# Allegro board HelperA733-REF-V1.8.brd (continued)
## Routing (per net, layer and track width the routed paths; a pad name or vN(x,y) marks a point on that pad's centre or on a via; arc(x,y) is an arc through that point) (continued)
PCIE-CLKREQN: length 35.6
  TOP w0.152: R229.2 44.01,60.15 43.66,60.5 Q10.2 43.66,63.45 43.61,63.5 v1(43.61,65.6) ; v1(61.01,65.5) 61.61,66.1 61.61,66.1 61.71,66.2 61.71,74.6 61.01,75.3 U1.131
  BOTTOM w0.152: v1(61.01,65.5) 60.11,66.4 48.73,66.4 47.11,64.78 44.43,64.78 v1(43.61,65.6)
PCIE-PERSTN: length 39.6
  TOP w0.152: U1.130 62.01,65.7 v1(61.81,65.5) ; v1(40.71,65.5) 40.56,65.35 Q11.2 40.56,60.68 R231.2
  BOTTOM w0.152: v1(40.71,65.5) 41.72,64.5 47.51,64.5 49.11,66.1 59.61,66.1 60.81,64.9 61.51,64.9 61.81,65.2 v1(61.81,65.5)
PCIE-WAKEN: length 29.3
  TOP w0.152: v1(61.01,66.4) 60.05,67.36 60.05,73.36 59.71,73.7 U1.132 ; R120.2 46.51,62.94 Q9.2 46.86,65.35 46.91,65.4 v1(46.91,65.3)
  BOTTOM w0.152: v1(46.91,65.3) 48.31,66.7 60.71,66.7 v1(61.01,66.4)
PERSTN: length 13.1
  TOP w0.152: J12.50 47.51,66.5 47.21,66.2 43.21,66.2 41.51,64.5 Q11.3 41.51,61.08 42.61,59.98 42.61,59.83 R232.2
PHYRSTB: length 23.3
  TOP w0.152: U10.12 110.92,76.7 110.02,75.8 CE7.2 109.44,76.17 ; 109.44,76.47 RE2.2 ; 109.44,76.47 109.44,76.32 ; 109.44,76.47 109.31,76.34 109.31,76.32 ; 109.44,76.32 109.31,76.32 ; 109.44,76.32 109.44,76.17 ; 109.44,76.17 109.29,76.32 ; 109.31,76.32 109.29,76.32 ; 109.29,76.32 107.05,76.32 106.34,75.61 101.66,75.61 99.91,77.36 93.67,77.36 93.01,76.7 U1.99
PK10: length 18.7
  TOP w0.152: J16.8 55.61,4.2 55.61,7 56.91,8.3 D57.6 D57.5 56.91,18.3 58.31,19.7 U1.186
PK11: length 15.4
  TOP w0.152: U1.187 58.21,18.7 57.41,17.9 D57.4 D57.7 57.41,8.2 56.11,6.9 56.11,5.7 J16.7
PK12: length 21.3
  TOP w0.152: U1.184 58.81,21.7 58.01,20.9 58.01,20.4 54.41,16.8 D58.2 D58.9 54.41,7.1 53.61,6.3 53.61,4.2 J16.10
PK13: length 17.9
  TOP w0.152: 58.81,20.7 U1.185 ; 58.81,20.7 54.91,16.8 D58.1 D58.10 54.91,6.9 54.11,6.1 54.11,5.7 J16.9 ; 58.81,20.7 58.73,20.7
PK16: length 16.7
  TOP w0.152: J16.6 57.61,4.2 57.61,6.2 58.42,7.01 58.42,8.5 58.41,8.51 D57.9 D57.2 58.41,12.5 59.71,13.8 62.31,13.8 63.01,14.5 U1.3
PK17: length 14.8
  TOP w0.152: U1.4 64.01,14.51 62.81,13.3 59.91,13.3 58.91,12.3 D57.1 D57.10 58.91,6.9 58.13,6.12 58.13,5.68 J16.5
PL12: length 37.9
  TOP w0.152: U1.171 58.81,34.7 57.41,33.3 57.41,20.8 53.61,17 v1(52.91,17) ; J16.16 47.61,4.2 47.61,7.6 48.91,8.9 D59.6 D59.5 48.91,13.6 v1(48.71,13.8)
  BOTTOM w0.152: v1(52.91,17) 51.91,17 v1(48.71,13.8)
PL13: length 37.1
  TOP w0.152: U1.170 58.81,35.7 57.11,34 57.11,20.88 53.83,17.6 v1(53.41,17.6) ; J16.15 48.13,5.68 48.13,7.52 49.41,8.8 D59.7 D59.4 49.41,14.1 v1(48.81,14.7)
  BOTTOM w0.152: v1(48.81,14.7) 49.21,14.7 52.11,17.6 v1(53.41,17.6)
PM5-BEEP: length 30.9
  TOP w0.152: v1(45.01,22.7) 45.01,24.7 44.49,25.23 R81.1 ; v1(56.51,22.6) 56.71,22.8 56.71,34.6 58.81,36.7 U1.169
  BOTTOM w0.152: v1(45.01,22.7) 46.31,21.4 50.71,21.4 51.41,22.1 56.01,22.1 v1(56.51,22.6)
PWRON: length 117.8
  TOP w0.152: v1(54.31,19) 55.9,20.59 55.9,23.39 56.41,23.9 56.41,35.68 58.43,37.7 U1.168 ; v1(102.91,14.64) 102.91,12.07 105.01,9.97 105.01,7.72 109.03,3.7 116.1,3.7 123.3,10.9 134.88,10.9 C46.1 135.19,10.07 135.15,10.04 D41.2 135.15,7.46 K2.2 135.31,7.62
  BOTTOM w0.152: v1(102.91,14.64) 102.3,15.26 98.06,15.26 94.8,18.52 55.35,18.52 54.87,19 v1(54.31,19)
REFCLKN: length 12.2
  TOP w0.152: 49.41,78.88 49.51,78.97 R235.1 49.41,78.9 ; 49.41,78.88 49.41,78.1 R333.1 49.23,77.75 49.23,77.3 49.31,77.23 49.85,77.23 50.35,76.73 50.35,73.75 50.05,73.44 48.65,73.44 48.38,73.71 48.38,74.24 48.26,74.36 J12.53 ; 49.41,78.88 49.41,78.9 ; 49.41,78.9 49.41,79.78 CB11.2 R237.2
REFCLKP: length 11.6
  TOP w0.152: R236.2 CB10.2 48.81,79.88 48.81,78.97 48.61,78.97 48.54,78.9 48.81,78.9 48.81,78.38 48.64,78.21 48.64,78.1 48.54,78.1 48.98,77.66 48.98,77.19 49.2,76.97 49.75,76.97 50.09,76.63 50.09,73.84 49.94,73.69 48.76,73.69 48.64,73.82 48.64,74.25 48.76,74.37 J12.55
RGMII0-CLK-25M: length 32.2
  TOP w0.203: R86.1 118.89,77.1 v1(118.89,77.1) ; v1(117.86,67.72) 117.66,67.72 115.49,65.55 103.15,65.55 99.31,61.7 U1.82
  BOTTOM w0.203: v1(118.89,77.1) 117.5,75.7 117.5,67.99 117.75,67.73 117.84,67.68 v1(117.86,67.72)
RGMII0-CLKIN-125M: length 29.7
  TOP w0.203: U1.83 99.28,62.7 102.62,66.04 115.18,66.04 117.55,68.41 v1(118.03,68.41) ; v1(118.84,74.48) 119.07,74.7 119.85,74.7 120.1,74.96 120.1,74.97 RE12.1
  BOTTOM w0.203: v1(118.03,68.41) 118.03,73.67 v1(118.84,74.48)
RGMII0-MDC: length 20.5
  TOP w0.152: U10.13 111.16,76.3 110.16,75.3 101.54,75.3 99.79,77.04 94.31,77.04 94.01,76.74 U1.98
RGMII0-MDIO: length 19.9
  TOP w0.152: U1.97 95.01,76.5 95.25,76.74 99.67,76.74 101.41,75 109.19,75 109.44,74.75 RE3.2 109.88,74.38 111.4,75.9 U10.14
RGMII0-RXCK: length 19.8
  TOP w0.152: 116.11,69.18 116.11,68.43 114.22,66.54 102.07,66.54 99.23,63.7 U1.84
RGMII0-RXCTL: length 18.2
  TOP w0.152: 115.01,69.18 115.01,68.6 113.26,66.84 101.46,66.84 99.31,64.7 U1.85
RGMII0-RXD0: length 20.7
  TOP w0.152: U1.86 99.29,65.7 100.74,67.15 112.1,67.15 113.33,68.38 113.33,69.51 RE9.1 114.51,71.72 U10.25
RGMII0-RXD1: length 19.9
  TOP w0.152: U10.24 114.11,71.88 112.76,70.53 112.21,70.53 RE8.1 112.26,69.48 112.26,68.36 111.36,67.46 99.97,67.46 99.21,66.7 U1.87
RGMII0-RXD2: length 18.9
  TOP w0.152: U1.88 99.08,67.77 110.43,67.77 111.18,68.51 111.18,69.46 RE5.1 111.43,70.83 112.48,70.83 113.71,72.07 U10.23
RGMII0-RXD3: length 18.5
  TOP w0.152: U10.22 113.31,72.1 112.35,71.14 110.78,71.14 109.66,70.03 RE13.1 110.01,69.53 110.01,68.43 109.65,68.07 99.83,68.07 99.25,68.66 99.05,68.66 U1.89
RGMII0-TXCK: length 10.3
  TOP w0.152: RE7.1 106.89,69.7 U1.90
RGMII0-TXCTL: length 10.3
  TOP w0.152: RE6.1 106.79,70.7 U1.91
RGMII0-TXD0: length 14.2
  TOP w0.152: U10.18 111.52,74.3 110.2,72.98 108.11,72.98 106.83,71.7 U1.92
RGMII0-TXD1: length 14
  TOP w0.152: U1.93 99.03,72.72 106.93,72.72 107.5,73.29 110.07,73.29 111.49,74.7 U10.17
RGMII0-TXD2: length 13.8
  TOP w0.152: U1.94 99.12,73.59 109.95,73.59 111.46,75.1 U10.16
RGMII0-TXD3: length 18.4
  TOP w0.152: U10.15 111.43,75.5 109.83,73.9 107.63,73.9 106.84,74.69 101.28,74.69 99.54,76.43 96.26,76.43 96.01,76.18 U1.96
RSET: length 3.9
  TOP w0.152: RE4.2 117.91,77.62 117.91,76.79 117.82,76.7 U10.39
RTC-IN: length 22.2
  TOP w0.152: U1.166 58.81,39.7 55.61,36.5 55.61,28.3 54.51,27.2 50.91,27.2 50.75,27.04 D37.2 50.21,26.6 50.01,26.4 J8.2
RXC/PHYAD1: length 4.2
  TOP w0.152: U10.27 115.31,70.83 RE10.2 RE14.2
RXCTL/PHYAD2: length 4.2
  TOP w0.152: RE11.2 RE15.2 114.91,71.03 U10.26
S-TWI0-CTP0-SCK: length 94.6
  TOP w0.152: J3.2 129.76,36.15 131.71,36.15 134.81,39.25 134.81,43.09 135.73,44.01 137.33,44.01 R25.1 138.11,43.53 138.31,43.73 138.88,43.73 139.07,43.53 D20.2 D20.9 140.78,43.53 141.01,43.3 J5.6 ; v1(64.51,32) 64.51,31.8 60.41,27.7 U1.178
  BOTTOM w0.152: J3.2 128.01,37.9 125.02,37.9 123,35.88 97.5,35.88 94.21,32.6 67.21,32.6 66.61,32 v1(64.51,32)
S-TWI0-CTP0-SDA: length 95.3
  TOP w0.152: J3.1 132.31,37.2 134.52,39.41 134.52,43.16 135.68,44.32 137.19,44.32 R24.1 138.14,44.93 139.04,44.03 D20.1 D20.10 140.85,44.03 141.28,43.6 141.73,43.6 141.91,43.78 142.61,43.78 J5.5 ; v1(65.11,32.6) 65.11,31.8 60.01,26.7 U1.179
  BOTTOM w0.152: v1(65.11,32.6) 66.71,32.6 67.11,33 94.11,33 97.31,36.2 122.88,36.2 124.88,38.2 129.71,38.2 J3.1
SDC0-CLK: length 47.1
  TOP w0.152: v1(95.66,72.94) 96.48,72.94 97,72.42 97,54.93 98.23,53.7 U1.74 ; v1(96.88,79.54) 96.88,83.07 99.32,85.51 103.42,85.51 104.56,86.65 D38.1 D38.10 104.56,88.89 104.24,89.21 102.97,89.21 102.76,89.42 102.76,90.45 J7.5
  BOTTOM w0.152: v1(95.66,72.94) 96.47,72.94 96.88,73.34 v1(96.88,79.54)
SDC0-CMD: length 40.8
  TOP w0.152: U1.75 98.21,54.7 97.45,55.46 97.45,72.99 96.88,73.56 v1(96.25,73.56) ; J7.3 100.56,88.21 D35.2 100.63,88.35 R52.2 99.23,88.35 98.99,88.12 98.99,86.38 96.27,83.66 v1(96.27,80.05)
  BOTTOM w0.152: v1(96.27,80.05) 96.25,80.07 v1(96.25,73.56)
SDC0-D0: length 45.5
  TOP w0.152: U1.73 97.79,52.7 96.51,53.98 96.51,72.09 v1(96.27,72.33) ; v1(97.49,80.05) 97.49,82.59 99.93,85.03 103.52,85.03 105.06,86.57 D38.2 D38.9 105.06,90.01 104.96,90.11 J7.7
  BOTTOM w0.152: v1(97.49,80.05) 97.49,73.34 96.47,72.33 v1(96.27,72.33)
SDC0-D1: length 47.6
  TOP w0.152: J7.8 106.06,89.87 106.16,89.77 D38.7 D38.4 106.16,87.12 103.64,84.6 100.29,84.6 98.2,82.5 v1(98.2,79.54) ; U1.72 98.06,51.7 96,53.76 96,70.56 96.17,70.73 96.17,71.41 v1(95.76,71.82)
  BOTTOM w0.152: v1(98.2,79.54) 98.2,73.45 96.58,71.82 v1(95.76,71.82)
SDC0-D2: length 38.5
  TOP w0.152: v1(95.08,74.59) 95.04,74.57 95.04,74.58 97.33,74.58 98.21,73.7 98.21,56.9 98.41,56.7 U1.77 ; J7.1 98.36,89.57 97.36,88.58 D33.2 95.15,86.17 v1(95.15,80.05)
  BOTTOM w0.152: v1(95.15,80.05) 95.15,74.59 v1(95.08,74.59)
SDC0-D3: length 39.2
  TOP w0.152: U1.76 98.21,55.7 97.83,56.08 97.83,73.48 97.24,74.07 95.71,74.07 v1(95.66,74.06) ; v1(95.66,79.54) 95.67,79.56 95.67,84.22 97.91,86.46 97.91,87.83 D34.2 98.41,88.52 99.46,89.57 J7.2
  BOTTOM w0.152: v1(95.66,74.06) 95.7,74.07 95.7,79.53 95.67,79.55 v1(95.66,79.54)
SDC0-DET: length 47.4
  TOP w0.152: D38.5 106.66,87.06 103.73,84.13 100.57,84.13 98.81,82.38 v1(98.81,80.05) ; D38.5 D38.6 ; D38.5 106.72,87.5 R53.1 ; v1(95.66,71.11) 95.56,71.01 95.56,53.46 98.33,50.7 U1.71
  BOTTOM w0.152: v1(95.66,71.11) 96.47,71.11 98.81,73.45 v1(98.81,80.05)
SPKR+: length 12
  TOP w0.381: 52.31,96.02 U8.8 ; 52.31,96.02 v1(52.82,96.53) 53.12,96.82 D45.2 53.98,98.19 53.98,99.86 J10.1 ; 52.31,96.02 52.31,96.07 ; v1(57.74,96.6) 57.74,95.99 57.79,95.99 CA22.1
  BOTTOM w0.381: v1(52.82,96.53) 52.89,96.6 v1(57.74,96.6)
SPKR-: length 10.5
  TOP w0.381: J10.2 55.18,100.65 54.51,99.98 54.51,98.07 55.25,97.33 D44.2 55.34,97.33 55.34,96.88 56.12,96.1 U8.5 56.12,95.1 CA25.1 57.79,93.3 R58.2
SPOLN: length 15.7
  TOP w0.152: UA1.12 65.78,88.28 65.47,88.58 v1(65.47,88.88) ; v1(58.13,88.4) 58.34,88.19 58.34,84.77 57.92,84.35 56.95,84.35 56.8,84.5 56.8,84.67 R59.1
  BOTTOM w0.152: v1(58.13,88.4) 59.03,87.5 63.88,87.5 65.19,88.8 65.39,88.8 v1(65.47,88.88)
SPOLP: length 19.8
  TOP w0.152: UA1.11 66.3,88.68 66.3,89.12 v1(66.27,89.12) ; R56.1 54.28,84.61 54.28,84.35 55.65,82.98 58.5,82.98 59.72,84.2 59.72,88.24 v1(59.92,88.44)
  BOTTOM w0.152: 66.15,89.12 66.27,89.12 v1(66.27,89.12) 66.27,89.7 66.11,89.87 64.67,89.87 63.51,88.7 60.19,88.7 v1(59.92,88.44)
SPORN: length 19
  TOP w0.152: v1(64.91,89.32) 65.22,89.63 66.61,89.63 66.81,89.43 UA1.10 ; R60.1 56.5,84.59 56.5,84.38 56.83,84.05 58.04,84.05 58.64,84.65 58.64,88.74 v1(58.11,89.27)
  BOTTOM w0.152: v1(58.11,89.27) 58.84,88.54 58.84,88.12 59.15,87.81 63.76,87.81 64.91,88.96 v1(64.91,89.32)
SPORP: length 20.4
  TOP w0.152: R57.1 54.58,84.65 54.58,84.48 55.78,83.28 58.36,83.28 59.41,84.33 59.41,88.77 v1(59.93,89.28) ; v1(66.56,90.14) 66.56,90.17 67.28,90.17 67.49,89.96 UA1.9
  BOTTOM w0.152: v1(59.93,89.28) 60.2,89.01 63.38,89.01 64.55,90.17 66.44,90.17 v1(66.56,90.14)
TRM-CTR: length 8.8
  TOP w0.152: J18.1 125.51,86.36 121.4,82.25 120.24,82.25 C62.2
TWI8-SCK: length 14.7
  TOP w0.152: U1.115 77.01,76.55 v1(77.02,76.57) ; UA1.32 71.92,85.48 72.17,85.22 72.17,82.76 RA22.1 72.03,81.95 72.03,81.23 72.32,80.94 75.13,80.94 v1(76.93,79.14)
  BOTTOM w0.152: v1(76.93,79.14) 76.6,78.82 76.6,76.99 v1(77.02,76.57)
TWI8-SDA: length 13.9
  TOP w0.152: U1.116 76.01,76.55 v1(76.01,76.55) ; v1(76.04,79.15) 76.04,79.6 75,80.64 72.19,80.64 71.73,81.1 71.73,81.91 RA23.1 71.87,83.08 71.87,84.95 71.74,85.08 UA1.31
  BOTTOM w0.152: v1(76.04,79.15) 76.35,78.84 76.35,76.89 v1(76.01,76.55)
TXC: length 3.6
  TOP w0.152: RE7.2 109.82,71.4 111.92,73.5 U10.20
TXCTL: length 3.3
  TOP w0.152: RE6.2 110.15,72.5 111.55,73.9 U10.19
UART0-RX: length 12.3
  TOP w0.152: U12.8 84.74,86.5 84.86,86.62 85.1,86.62 85.38,86.34 85.38,76.27 85.01,75.9 U1.107
UART0-TX: length 12.7
  TOP w0.152: U1.106 86.01,75.9 85.64,76.27 85.64,86.44 85.2,86.88 84.86,86.88 84.74,87 U12.9
UART2-RX: length 76.7
  TOP w0.152: U1.105 91.95,70.76 91.95,23.89 90.11,22.04 v1(90.11,21.4) ; D51.1 105.11,20.3 v1(105.81,21) 106.91,22.1 R69.1
  BOTTOM w0.152: v1(90.11,21.4) 90.48,21.4 90.78,21.1 99.15,21.1 99.25,21 v1(105.81,21)
UART2-TX: length 76.4
  TOP w0.152: 110.01,21.37 109.78,21.6 107.79,21.6 R74.2 107.29,21 v1(106.61,21) ; U1.104 88.01,75.12 92.21,70.92 92.21,23.73 90.71,22.24 v1(90.71,21.9)
  BOTTOM w0.152: v1(90.71,21.9) 91.21,21.4 105.35,21.4 105.55,21.6 106.01,21.6 v1(106.61,21)
UART3-RX: length 124.9
  TOP w0.152: R77.2 44.51,16.8 ; 44.51,16.8 43.61,17.7 41.51,17.7 41.41,17.6 D55.2 D55.9 41.41,15.6 41.5,15.51 41.5,11.95 39.19,9.64 38.48,9.64 37.62,8.78 37.62,6.82 J14.3 ; 44.51,16.8 v1(44.61,16.9) ; U1.101 91.01,73.51 92.97,71.55 92.97,22.04 91.41,20.48 v1(91.41,19.5)
  BOTTOM w0.152: v1(44.61,16.9) 50.21,16.9 53.21,19.9 54.91,19.9 55.72,19.09 91,19.09 v1(91.41,19.5)
UART3-TX: length 121.4
  TOP w0.152: v1(92.21,19.5) 91.91,19.8 91.91,20.6 93.22,21.91 93.22,71.73 92.01,72.94 U1.100 ; J14.2 41.91,11.67 D55.10 D55.1 41.91,17.27 42.06,17.42 43.09,17.42 v1(44.51,16) R78.2
  BOTTOM w0.152: v1(92.21,19.5) 91.55,18.84 55.6,18.84 54.84,19.6 53.35,19.6 49.75,16 v1(44.51,16)
UART4-RX: length 126.5
  TOP w0.152: U1.103 89.01,74.57 92.46,71.12 92.46,22.25 v1(89.81,19.6) ; J15.3 35.51,9.13 35.51,10.6 37.71,12.8 39.41,12.8 40.36,13.75 40.36,15.4 40.41,15.45 D55.7 D55.4 40.41,17.5 40.91,18 43.71,18 44.01,17.7 v1(44.71,17.7) 45.29,17.7 R79.2
  BOTTOM w0.152: v1(44.71,17.7) 50.56,17.7 53.06,20.2 55.11,20.2 55.91,19.4 89.18,19.4 89.38,19.6 v1(89.81,19.6)
UART4-TX: length 126
  TOP w0.152: 44.51,18.3 45.19,18.3 R80.2 ; 44.51,18.3 40.71,18.3 39.91,17.5 D55.5 D55.6 39.91,14.05 39.86,14.05 39.01,13.2 37.61,13.2 35.11,10.7 35.11,9.4 34.08,8.37 J15.2 ; 44.51,18.3 v1(44.51,18.4) ; v1(90.61,19.6) 90.61,20.04 92.71,22.14 92.71,71.33 90.01,74.03 U1.102
  BOTTOM w0.152: v1(44.51,18.4) 50.81,18.4 52.91,20.5 55.31,20.5 56.11,19.7 89.04,19.7 89.54,20.2 90.01,20.2 v1(90.61,19.6)
UPUSB-DM: length 13.8
  TOP w0.254: 83.21,96.3 83.83,95.67 83.83,94.92 82.14,93.23 82.14,90.93 81.88,90.68 81.03,90.68 80.98,90.73 U11.5 ; 83.21,96.3 D62.1 ; 83.21,96.3 83.21,96.31 84.06,97.16 J19.A7 84.06,98.93 84.11,99.5 84.31,99.7 84.81,99.7 85.06,99.45 J19.B7
UPUSB-DP: length 14.4
  TOP w0.254: v1(84.81,97.1) 84.84,97.1 ; J19.A6 84.56,97.25 84.81,97 D61.1 84.81,96.21 84.77,96.25 84.19,95.67 84.19,94.78 82.49,93.08 82.49,90.78 82,90.29 81.04,90.29 80.96,90.21 U11.6 ; 83.11,97 v1(83.21,97.1) 83.56,97.45 J19.B6
  BOTTOM w0.254: v1(83.21,97.1) v1(84.81,97.1)
USB0-DM: length 29.2
  TOP w0.254: 80.51,92.86 79.36,92.86 v1(79.21,93) ; v1(74.91,73.9) 74.69,74.12 74.69,75.18 75.01,75.5 U1.117
  BOTTOM w0.254: v1(79.21,93) 79.41,92.8 80.21,92.8 80.79,92.22 80.79,75.95 79.86,75.02 74.84,75.02 74.69,74.87 74.69,74.12 v1(74.91,73.9)
USB0-DP: length 28.6
  TOP w0.254: U11.2 79.34,92.33 v1(79.21,92.2) ; v1(74.11,73.9) 74.33,74.12 74.33,75.18 74.01,75.5 U1.118
  BOTTOM w0.254: v1(79.21,92.2) 79.26,92.15 79.55,92.44 80.06,92.44 80.43,92.07 80.43,76.1 79.71,75.38 74.7,75.38 74.33,75.02 74.33,74.12 v1(74.11,73.9)
USB1-DM: length 66.5
  TOP w0.254: U42.5 14.81,81.94 14.9,81.85 15.63,81.85 16.25,81.23 16.25,80.43 17.68,79 31.27,79 34.23,81.97 38.68,81.97 39.42,82.71 41.43,82.71 43.44,82.71 44.64,83.9 51.67,83.9 55.21,80.37 62.39,80.37 63.62,79.13 68.84,79.13 70.54,77.42 72.11,77.42 72.67,76.87 72.67,76.33 73.01,75.99 U1.119
USB1-DP: length 65.9
  TOP w0.254: U1.120 72.01,76.09 72.29,76.38 72.29,76.74 71.96,77.07 70.4,77.07 68.69,78.77 63.48,78.77 62.24,80.01 55.06,80.01 51.53,83.54 44.79,83.54 43.6,82.35 39.57,82.35 38.83,81.61 34.39,81.61 31.42,78.65 17.53,78.65 15.9,80.28 15.9,81.08 15.48,81.49 14.9,81.49 14.81,81.41 U42.6
USB2-DM: length 82.8
  TOP w0.254: CON3.36 11.11,64.3 10.71,63.9 v1(10.31,63.9) ; U1.123 69.01,75.89 68.69,76.21 68.69,77.46 67.73,78.42 63.14,78.42 62.04,79.52 54.99,79.52 51.32,83.18 44.96,83.18 43.77,81.99 39.72,81.99 38.98,81.25 38.6,81.25 34.53,81.25 31.57,78.29 13.52,78.29 v1(13.21,78.6)
  BOTTOM w0.254: v1(10.31,63.9) 9.71,64.5 9.71,77.69 10.4,78.38 12.99,78.38 v1(13.21,78.6)
USB2-DP: length 79.2
  TOP w0.254: v1(10.31,64.7) CON3.38 ; U1.124 68.01,75.9 68.33,76.22 68.33,77.31 67.58,78.06 62.99,78.06 61.9,79.16 54.84,79.16 51.17,82.83 45.13,82.83 43.94,81.64 39.87,81.64 39.12,80.9 38.75,80.9 34.68,80.9 31.72,77.93 13.34,77.93 v1(13.21,77.8)
  BOTTOM w0.254: v1(10.31,64.7) 10.07,64.94 10.07,77.55 10.54,78.02 12.99,78.02 v1(13.21,77.8)
USIM_CLK: length 13.4
  TOP w0.152: J21.3 15.81,61.45 17.16,60.1 D72.7 D72.4 20.01,60.1 23.91,64 CON3.12
USIM_DATA: length 14.7
  TOP w0.152: CON3.10 24.71,63.68 20.13,59.1 D72.2 D72.9 16.51,59.1 15.51,60.1 15.21,60.1 15.13,60.18 J21.7
USIM_RST: length 17.9
  TOP w0.152: CON3.14 23.11,64.4 19.31,60.6 D72.5 D72.6 17.61,60.6 15.91,62.3 14.01,62.3 13.61,61.9 13.61,59.2 13.9,58.91 J21.2
USIM_VCC: length 17.1
  TOP w0.152: J21.1 16.08,56.37 16.61,56.9 16.61,58.2 17.01,58.6 D72.10 D72.1 20.61,58.6 25.51,63.5 CON3.8
VCOM: length 4.8
  TOP w0.152: R30.2 R36.1 141.21,73.8 142.11,72.9 J4.1
VDD-CORE/HP-DET: length 3.5
  TOP w0.203: UA1.35 72.07,86.68
  TOP w0.254: 73.67,86.21 73.67,86.2 RA11.1 ; 73.67,86.21 73.67,87.17 73.64,87.2 CA11.1 ; 73.67,86.21 73.35,86.21 72.89,86.68 72.07,86.68
VGH: length 31.4
  TOP w0.305: 144.41,54.4 J4.38
  TOP w0.5: 144.41,54.4 144.71,54.4 148.11,57.8 148.11,76.01 147.81,76.31 143.3,76.31 142.91,76.7 C31.1
VGL: length 32.6
  TOP w0.152: C35.1 136.19,76.13 C34.1 135.31,76.79 v1(135.71,77.9)
  TOP w0.305: v1(144.04,55.91) 144.04,55.9 J4.35
  BOTTOM w0.5: v1(144.04,55.91) 144.62,55.91 145.71,57 145.71,69.8 137.61,77.9 v1(135.71,77.9)
VRA1/MIC2P: length 2.9
  TOP w0.152: UA1.14 65.61,87.48 64.79,88.3 63.84,88.3 63.84,88.4
VRA2/MIC2N: length 4.4
  TOP w0.152: 63.84,90.5 63.84,89.55 63.68,89.4 63.84,89.4 64.6,88.64 64.88,88.64 65.65,87.88 UA1.13
W_DISABLE_N: length 4.3
  TOP w0.3: CON3.20 17.51,64.28 18.87,62.92 18.87,62.64 18.84,62.64 R100.1
WAKEN: length 8.1
  TOP w0.152: R228.2 Q9.3 47.81,64.4 48.51,65.1 J12.54
XTAL-25MIN: length 8.3
  TOP w0.203: X1.3 124.29,75.56 123.63,76.22 122.2,76.22 CE15.2 121.23,75.8 119.02,75.8 118.71,75.5 U10.36
XTAL-25MOUT: length 6.8
  TOP w0.203: U10.37 118.61,75.9 118.87,76.16 120.17,76.16 120.35,76.33 120.35,76.85 R86.2 121.34,77.1 CE14.2 122.64,77.28 X1.1
N39839: length 3.3
  TOP w0.152: J7.9 107.16,88.75 R53.2 R51.2
N638326: length 23
  TOP w0.152: J18.14 117.21,97.26 117.21,95.6 110.51,88.9 110.51,83.68 110.03,83.2 R85.1
N638520: length 35.2
  TOP w0.152: J18.11 122.31,96.77 122.31,94.7 126.97,90.04 126.97,79.66 126.31,79 126.31,74.29 125.12,73.1 R82.1
N5679096: length 2.2
  TOP w0.3: C1.1 16.62,23.82 16.4,24.04 16.4,24.89
N5679154: length 3.9
  TOP w0.152: U2.3 14.5,25.14 14.35,25.29 R7.1 R4.2 C4.2
N16925291: length 3.6
  TOP w0.152: L5.2 135.41,96.8 136.51,97.92 D32.1
N17131711: length 7.4
  TOP w0.152: 126.61,23.68 128.84,23.68 129.11,23.4 129.11,22.95 D70.2
N17175777: length 12.1
  TOP w0.508: R72.1 R71.2 112.51,21.37 U9.2 112.55,19.9 112.19,19.54 111.58,19.54 ; 111.58,19.54 111.22,19.54 ; 111.58,19.54 111.28,19.85 ; 111.22,19.54 111,19.54 ; 111.22,19.54 111.28,19.59 111.28,19.81 ; 111.28,19.81 111,19.54 ; 111.28,19.81 111.28,19.85 ; 111.28,19.85 U9.3 ; 111,19.54 Q1.3
N17175783: length 12.9
  TOP w0.152: U9.1 113.82,19.95 112.91,19.04 110.21,19.04 109.67,18.5 108.21,18.5 107.71,18 107.71,17 107.31,16.6 105.23,16.6 105.11,16.72 D51.2
N17177153: length 4.6
  TOP w0.152: U3.3 25.96,48.45 26.01,48.4 C11.2 R9.2 26.31,46.98 26.31,46.83 R11.1
N17255318: length 3.4
  TOP w0.152: Q2.1 45.31,23.24 45.31,25.13 45.32,25.13 45.34,25.15 R81.2
N17255336: length 11.1
  TOP w0.5: Q2.3 39.22,23.5 38.54,24.18 J17.2
  TOP w0.6: Q2.3 43.97,22.62 45.83,20.77 D56.1
N17819196: length 5.6
  TOP w0.152: CA18.1 64.63,84 65.71,85.08 UA1.20 66.88,85.08 67.02,85.22 67.02,86.54 66.88,86.68 UA1.16
N17819206: length 2.3
  TOP w0.152: CA19.1 67.89,83.5 UA1.23
N17819214: length 3.6
  TOP w0.152: CA19.2 66.3,82.08 66.3,83.05 v1(66.33,83.05) ; v1(66.65,84.18) 66.65,84.18 67.09,84.18 UA1.21
  BOTTOM w0.152: v1(66.33,83.05) 66.32,83.07 66.57,83.33 66.57,84.18 v1(66.65,84.18)
N17819230: length 2.7
  TOP w0.152: UA1.34 72.37,86.28 73.35,85.3 73.59,85.3 CA17.1
N17819689: length 4.7
  TOP w0.152: RA5.2 71.76,98.08 71.76,97.03 71.91,97.03 CA7.1 ; CA5.2 CA6.2 71.78,96.03 71.78,96.97 71.91,96.97 CA7.1 ; CA7.1 RA3.2
N17819691: length 5.2
  TOP w0.152: RA6.2 71.09,98 71.19,98 71.19,97 ; 71.19,97 CA7.2 CA12.1 ; 71.19,97 71.21,97 71.21,95.99 71.09,95.99 71.01,95.91 CA9.2 71.12,96.03 71.05,96.1
  TOP w0.25: 71.05,96.1 RA10.2
N17819723: length 28.9
  TOP w0.25: RA12.1 RA10.1 68.72,96.1 68.33,96.49 68.33,97.81 67.79,98.35 63.11,98.35 62.21,99.26 62.21,102.29 63.13,103.21 73.16,103.21 74.92,101.44 74.92,100.12 CA8.2
N17819725: length 2.4
  TOP w0.25: RA1.1 73.84,96.1 RA3.1 74.41,97.58 CA8.1
N17838408: length 1.2
  TOP w0.152: R66.1 C55.2
N17838410: length 1.2
  TOP w0.152: R68.1 C56.2
N17838457: length 14.2
  TOP w0.152: 38.26,90.98 38.81,90.98 R63.2 ; 38.26,90.98 38.26,92.1 38.86,92.7 42.42,92.7 43.21,91.91 ; 38.26,90.98 37.71,90.98 R67.1 ; 43.21,91.91 D48.2 42.73,91.37 42.73,90.31 C52.1 ; 43.21,91.91 43.21,95.2 J11.3
N17838500: length 11.5
  TOP w0.152: C53.1 44.13,90.31 44.13,91.34 44.61,91.82 D50.2 44.61,92.8 45.64,93.83 45.64,98.33 44.48,99.49 J11.4
N17838683: length 3.4
  TOP w0.152: R63.1 39.91,91.83 D49.2 41.01,91.86 R61.2 R62.2
N17845378: length 2.2
  TOP w0.381: C48.2 R57.2 R56.2
N17845396: length 2.2
  TOP w0.381: R59.2 R60.2 C50.2
N17845478: length 1.8
  TOP w0.381: U8.3 54.85,87.93 C48.1
N17845505: length 4.8
  TOP w0.381: C50.1 56.12,87.93 U8.4 56.12,90.79 R58.1
N17845570: length 1.8
  TOP w0.381: U8.2 53.58,87.93 C47.1
N17874598: length 4.6
  TOP w0.152: RA27.1 62.41,96.03 ; 62.41,96.03 62.41,96 63.41,96 CA20.2 63.49,96.1 63.49,96 64.49,96 CA21.1 ; 62.41,96.03 CA23.1 61.51,96 60.54,96
N17874616: length 5.1
  TOP w0.152: 62.41,95.3 61.56,95.3 CA23.2 61.61,95.2 60.64,95.2 60.54,95.1 ; 62.41,95.3 RA30.2 ; 62.41,95.3 63.41,95.3 ; 63.41,95.3 64.59,95.3 64.59,95.12 64.61,95.1 CA24.1 ; 63.41,95.3 CA26.1
N17874634: length 1.1
  TOP w0.152: RA28.1 CA22.2
N17874636: length 1.1
  TOP w0.152: RA29.1 CA25.2
N17914651: length 4.3
  TOP w0.152: C29.2 138.21,86.97 D31.1 137.55,87.92 137.57,87.9 136.61,87.9 L4.2
N17914697: length 3
  TOP w0.152: U6.3 136.7,93.75 137.05,94.1 R42.1 R39.1
N17915278: length 6.1
  TOP w0.152: J4.6 141.87,70.4 140.82,71.45 139.6,71.45 139.58,71.42 138.76,71.42 R17.2 R18.1
N17963617: length 1.3
  TOP w0.152: RU2.2 26.59,82.12 U13.3
N17967469: length 6.2
  TOP w0.203: X2.1 86.26,95.8 85.91,95.45 85.91,95.32 85.08,94.49 85.08,91.11 84.71,90.73 U11.12
N17967471: length 7.9
  TOP w0.203: X2.3 87.96,93.6 87.06,94.5 85.6,94.5 85.41,94.31 85.41,90.9 84.71,90.21 U11.11
N17967477: length 4.1
  TOP w0.152: 87.29,91.9 86.71,91.9 85.92,91.1 85.92,90.68 84.91,89.68 84.31,89.68
N18037700: length 2.3
  TOP w0.152: R233.2 18.89,48.45 U3.4
N18103307: length 3.5
  TOP w0.152: CB4.2 46.39,77.75 46.39,77.35 47.14,76.6 47.14,75.86 47.26,75.73 J12.49
N18103321: length 3.5
  TOP w0.152: CB5.2 46.13,77.75 46.13,77.24 46.88,76.49 46.88,75.87 46.76,75.74 J12.47
N18104730: length 3.9
  TOP w0.152: R21.2 10.11,40.1 9.16,39.15 CON2.17
N18104732: length 3.7
  TOP w0.152: CON2.22 10.34,41.65 R22.2
N18104734: length 3.9
  TOP w0.152: R26.2 9.84,42.15 CON2.23
N18105041: length 6.1
  TOP w0.152: CON2.3 7.66,32.15 7.78,32.27 10.98,32.27 11.52,31.73 12.32,31.73 12.73,31.32 12.77,31.32 C21.2
N18105043: length 6.1
  TOP w0.152: C22.2 12.77,32.4 12.73,32.4 12.32,31.98 11.63,31.98 11.08,32.53 7.78,32.53 7.66,32.65 CON2.4
N18105045: length 6
  TOP w0.152: C25.2 12.39,35.73 11.83,35.73 11.38,35.27 7.78,35.27 7.66,35.15 CON2.9
N18105047: length 6
  TOP w0.152: C28.2 12.39,35.98 11.73,35.98 11.27,35.53 7.78,35.53 7.66,35.65 CON2.10
N18105049: length 5.8
  TOP w0.152: C23.2 12.35,33.77 7.78,33.77 7.66,33.65 CON2.6
N18105059: length 5.9
  TOP w0.152: CON2.7 7.66,34.15 7.78,34.03 12.44,34.03 12.66,34.25 12.77,34.25 C24.2
N18142204: length 26
  TOP w0.152: R101.1 1.41,80.4 1.11,80.1 1.11,78.4 1.51,78 3.31,78 3.61,77.7 3.61,73.3 5.31,71.6 5.31,70.5 3.71,68.9 3.71,65 4.01,64.7 8.51,64.7 8.71,64.9 CON3.42
N18142206: length 1.7
  TOP w0.152: R101.2 2.74,79.69 D73.2
N18142901: length 5.5
  TOP w0.152: U42.12 18.73,81.94 19.39,82.6 21.86,82.6 22.71,83.45 X3.1
N18142903: length 2.6
  TOP w0.152: U42.11 19.02,81.41 19.36,81.75 X3.3
N18142917: length 2.5
  TOP w0.152: C86.1 19.21,80.4 18.74,80.88 U42.10
N18148344: length 3.8
  TOP w0.152: R116.1 C92.2 R117.2 24.21,57.6 24.16,57.55 U43.3
N18193662: length 10.6
  TOP w0.152: 47.81,58.88 47.25,58.31 45.77,58.31 45.21,58.88 44.63,58.3 43.29,58.3 42.71,58.88 42.23,58.4 39.58,58.4 38.83,59.15 D84.2
N18243800: length 3.2
  TOP w0.152: U44.1 20.86,16.3 20.96,16.4 R158.1 R157.2
N18243874: length 4.9
  TOP w0.152: 20.45,10.5 20.44,10.5 20.31,10.38 ; 20.45,10.5 20.45,10.38 ; 20.45,10.5 20.45,10.5 20.57,10.38 ; 20.45,10.5 20.45,12.27 20.01,12.7 U44.5 ; 20.45,10.38 20.57,10.38 ; 20.45,10.38 20.31,10.38 ; 20.57,10.38 21.05,10.38 C323.2 ; 20.31,10.38 R159.2
N18245140: length 18.7
  TOP w0.152: R238.1 R239.2 22.89,8.68 20.41,6.2 19.61,6.2 18.81,5.4 18.81,3.7 18.01,2.9 15.51,2.9 14.51,3.9 14.47,3.9 14.11,4.26 J2.3
N18245142: length 16.4
  TOP w0.152: J2.2 17.11,4.74 19.17,6.8 20.31,6.8 22.32,8.81 22.32,15 22.02,15.3 20.66,15.3 20.01,15.95 U44.2
N18248395: length 2.9
  TOP w0.152: R6.2 25.31,17.2 25.35,17.24 D2.1 R240.1
N18249325: length 1.4
  TOP w0.152: R241.2 27.11,17.16 D2.2
N18257684: length 4.1
  TOP w0.152: R242.2 43.94,77.8 43.94,77.54 44.57,76.91 44.91,76.91 45.64,76.18 45.64,75.86 45.76,75.74 J12.43
N18257704: length 4.1
  TOP w0.152: J12.41 45.26,75.75 45.38,75.87 45.38,76.08 44.81,76.65 44.45,76.65 43.68,77.42 43.68,77.8 R243.2
N171758202: length 4.5
  TOP w0.152: R74.1 107.54,20.5 107.25,20.5 106.61,19.86 106.61,17.51 Q1.1
N171758280: length 1
  TOP w0.508: R71.1 C61.2
N171771995: length 2.1
  TOP w0.3: C8.1 22.84,46.23 23.16,46.55 U3.1
N181483905: length 2.1
  TOP w0.3: U43.1 23.29,55.65 22.84,55.2 C89.1
N182437470: length 1.4
  TOP w0.6: C322.1 R156.1

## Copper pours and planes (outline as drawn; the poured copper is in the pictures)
5V on TOP (solid shape): 38.91,33.8 37.31,33.8 37.31,35.3 38.91,35.3
5V on TOP (solid shape): 133.51,97.8 130.41,97.8 130.41,99.9 133.51,99.9
5V on TOP (solid shape): 133.51,89.6 130.51,89.6 130.51,92.5 133.51,92.5
5V on TOP (solid shape): 24.31,27 24.31,24.4 19.71,24.4 19.71,25.5 20.71,26.5 20.71,27.1 24.21,27.1
5V on TOP (solid shape): 53.51,40.74 53.51,36.3 53.11,35.9 51.91,35.9 51.51,36.3 51.51,40.74 51.61,40.84 53.41,40.84
5V on BOTTOM (solid shape): 53.51,35.55 49.66,35.55 47.71,33.6 37.31,33.6 37.31,35.4 46.11,35.4 48.11,37.4 53.51,37.4
12V-IN on TOP (solid shape): 15.75,15.5 15.75,13.64 16.21,13.18 17.44,13.18 17.56,13.3 17.56,13.95 17.81,14.2 19.46,14.2 19.46,12.45 20.05,11.86 20.05,11.33 19.54,11.33 19.49,11.28 19.05,11.73 18.02,11.73 17.59,11.3 17.59,10.33 17.31,10.05 13.56,10.05 12.21,11.4 12.21,15.87 15.38,15.87
AVDD on TOP (solid shape): 141.84,88.8 141.74,88.7 140.84,88.7 140.74,88.6 140.74,88.4 140.84,88.3 141.74,88.3 141.84,88.2 141.84,87 141.74,86.9 139.04,86.9 138.94,87 138.94,88.5 138.84,88.6 137.34,88.6 137.24,88.7 137.24,90 137.34,90.1 141.84,90.1
AVDD33 on TOP (solid shape): 110.49,82.18 110.49,78.83 111.33,77.99 112.52,77.99 112.62,77.89 112.62,77.08 112.52,76.98 110.18,76.98 109.47,77.69 109.23,77.69 109.18,77.75 109.18,80.52 108.56,81.14 108.56,82.16 108.66,82.26 110.42,82.26
AVDD33 on BOTTOM (solid shape): 110.77,82.01 110.77,79.17 110.67,79.07 109.14,79.07 109.04,79.17 109.04,82.01 109.14,82.11 110.67,82.11
GND on TOP (solid shape): 88.68,38.09 84.62,38.09 84.62,44.33 88.68,44.33
GND on TOP (solid shape): 15.08,68.17 15.13,68.15 15.14,68.11 15.14,67.86 15.15,67.74 15.18,67.63 15.17,67.57 15.12,67.55 14.81,67.55 14.77,67.54 14.65,67.54 14.62,67.55 14.01,67.55 13.97,67.54 13.85,67.54 13.82,67.55 13.21,67.55 13.17,67.54 13.05,67.54 13.02,67.55 12.41,67.55 12.37,67.54 12.25,67.54 12.22,67.55 11.61,67.55 11.57,67.54 11.45,67.54 11.42,67.55 10.81,67.55 10.77,67.54 10.65,67.54 10.62,67.55 10.01,67.55 9.97,67.54 9.85,67.54 9.82,67.55 9.21,67.55 9.17,67.54 9.05,67.54 9.02,67.55 8.41,67.55 8.37,67.54 8.25,67.54 8.22,67.55 7.61,67.55 7.57,67.54 7.45,67.54 7.42,67.55 6.81,67.55 6.77,67.54 6.65,67.54 6.62,67.55 6.01,67.55 5.97,67.54 5.85,67.54 5.82,67.55 5.46,67.55 5.4,67.58 5.42,67.65 5.44,67.67 5.92,68.15 5.94,68.17 5.96,68.17
GND on TOP (solid shape): outline of 590 points within 136.49,76.69 148.24,94.14
GND on TOP (solid shape): outline of 279 points within 51.02,60.62 64.04,80.25
GND on TOP (solid shape): outline of 703 points within 133.43,72.67 145.24,85.53
GND on TOP (solid shape): outline of 363 points within 99.14,5.88 130.48,26.28
GND on TOP (solid shape): outline of 1056 points within 7.58,80.17 24.89,99.06
GND on TOP (solid shape): outline of 10143 points within 0.57,46.51 149.43,104.43
GND on TOP (solid shape): outline of 14051 points within 0.57,0.57 149.43,75.18
GND on BOTTOM (solid shape): outline of 19536 points within 0.57,0.57 149.43,104.43
VCC_4G on TOP (solid shape): 29.18,49.93 27.82,49.93 27.71,50.04 27.71,51.03 27.64,51.1 25.08,51.1 25.01,51.03 25.01,49.77 23.92,49.77 23.92,53.28 26.74,53.28 27.24,53.78 27.24,56.23 27.14,56.33 26.89,56.33 26.62,56.6 26.62,58.06 26.74,58.18 29.18,58.18
DCIN on TOP (solid shape): 6.41,45.4 6.41,43.6 6.15,43.33 4.95,43.33 4.71,43.57 4.71,45.4 4.81,45.5 6.31,45.5
DCIN on TOP (solid shape): 15.81,21.2 16.31,20.7 16.31,20.3 14.51,20.3 14.51,20.7 15.11,21.3 15.11,22.2 15.81,22.2
DCIN on TOP (solid shape): 20.06,20.45 20.06,19.5 20.39,19.18 20.39,18 19.5,17.11 19.5,15.7 19.4,15.61 18.11,15.61 17.81,15.9 17.81,17.9 17.51,18.2 15.11,18.2 14.26,19.05 14.26,20.8 19.71,20.8
DCIN on TOP (solid shape): 20.43,56.87 21.62,56.87 21.62,56.34 20.51,56.34 20.09,55.92 20.09,55.91 19.48,55.3 19.48,51.95 17.14,51.95 16.71,52.38 16.71,54.02 18.53,55.84 18.53,56.36 18.54,56.36 18.54,56.95 18.68,57.08 20.23,57.08
DCIN on TOP (solid shape): 19.22,51.83 17.51,51.83 16.97,51.29 16.97,47.95 17.12,47.8 20.44,47.8 20.56,47.78 21.6,47.78 21.6,47.22 20.53,47.22 20.21,46.91 20.21,45.51 19.15,44.45 19.15,43 17.05,43 15.05,44.99 10.48,44.99 9.91,44.43 9.91,43.68 9.86,43.57 9.76,43.53 4.71,43.53 4.71,45.22 4.79,45.3 8.3,45.3 8.72,45.73 8.59,45.86 8.59,48.68 9.03,49.12 14.58,49.12 14.77,49.31 14.77,52.74 15.17,53.14 15.85,53.14 16.76,54.05 19.22,54.05
PCIE-3V3 on TOP (solid shape): 26.77,19.15 24.94,19.15 24.94,19.76 26.77,19.76
PCIE-3V3 on TOP (solid shape): 39.91,66.3 39.91,63.2 39.81,63.1 35.56,63.1 35.26,63.4 35.26,66.25 35.41,66.4 39.81,66.4
PCIE-3V3 on TOP (solid shape): 53.81,64.9 52.71,64.9 51.81,64 51.81,63.2 49.86,63.2 49.86,65.85 50.51,66.5 53.81,66.5
PCIE-3V3 on TOP (solid shape): 35.89,63.38 34.91,62.4 34.91,48.1 34.31,47.5 29.41,47.5 29.01,47.1 27.11,47.1 27.11,49.1 32.71,49.1 33.11,49.5 33.11,65.1 33.91,65.9 35.89,65.9
PCIE-3V3 on TOP (solid shape): 29.25,48.97 29.25,40.54 27.45,40.54 27.19,40.81 27.19,42.04 27.12,42.1 25.36,42.1 25.32,42.07 25.32,40.89 23.36,40.89 23.36,44.14 26.78,44.14 27.36,44.72 27.36,46.94 27.2,47.1 26.5,47.1 26.5,49.13 29.09,49.13
PCIE-3V3 on BOTTOM (solid shape): 53.76,65.65 53.76,64.7 53.64,64.58 52.31,64.58 50.54,62.8 48.97,62.8 48.89,62.72 36.21,62.72 35.77,63.16 35.77,65.5 39.71,65.5 41.01,64.2 47.61,64.2 49.21,65.8 53.61,65.8
REGOUT on TOP (solid shape): 117.19,73.12 117.19,71.85 117.45,71.59 120.75,71.59 120.95,71.39 120.95,68.85 120.85,68.75 120.04,68.75 119.93,68.85 119.93,70.48 119.53,70.88 116.78,70.88 116.38,71.29 116.38,73.12 116.48,73.22 117.09,73.22
S-TWI0-CTP0-SDA on BOTTOM (solid shape): 129.64,38.19 129.66,38.25 129.72,38.27 131.47,37.96 130.72,37.19 129.95,36.44
VGH on TOP (solid shape): 143.24,81.8 143.24,77.4 143.14,77.3 141.94,77.3 141.84,77.4 141.84,80.1 141.74,80.2 140.64,80.2 140.54,80.3 140.54,81.8 140.64,81.9 143.14,81.9
VGL on TOP (solid shape): 134.54,80.7 134.54,80 134.64,79.9 136.04,79.9 136.14,79.8 136.14,75.6 136.04,75.5 134.84,75.5 134.74,75.6 134.74,78.9 134.64,79 133.54,79 133.44,79.1 133.44,80.7 133.54,80.8 134.44,80.8
XTAL-25MIN on TOP (solid shape): 123.59,76.14 123.62,76.23 123.71,76.26 125.26,75.9 124.68,75.18 124.06,74.5
N5679088 on TOP (solid shape): 18.61,22.7 21.81,22.7 21.81,21.25 16.46,21.25 16.21,21.5 16.21,22.95 16.41,23.15 18.16,23.15
N16925291 on TOP (solid shape): 138.61,97.5 135.21,97.5 135.21,99.9 138.61,99.9
N17177143 on TOP (solid shape): 22.31,46.3 22.31,44.9 21.61,44.2 21.61,40.7 19.61,40.7 19.61,44.55 20.46,45.4 20.46,46.8 21.81,46.8
N17914651 on TOP (solid shape): 136.61,89.2 135.11,89.2 135.11,92 136.61,92
N17914651 on TOP (solid shape): 138.31,85.8 134.91,85.8 134.91,86.6 135.11,86.6 135.11,88.1 138.31,88.1
N17914681 on TOP (solid shape): 140.04,86.3 140.04,84.1 139.94,84 138.54,84 138.44,84.1 138.44,85.3 138.74,85.6 138.74,86.3 138.84,86.4 139.94,86.4
N17914691 on TOP (solid shape): 134.94,83 134.94,81.9 135.04,81.8 135.84,81.8 135.94,81.7 135.94,80.3 135.84,80.2 134.94,80.2 134.84,80.3 134.84,80.9 134.74,81 133.54,81 133.44,81.1 133.44,83 133.54,83.1 134.84,83.1
N17914762 on TOP (solid shape): 142.9,83.68 142.9,82.38 142.7,82.18 139.45,82.18 139.34,82.29 139.34,82.97 139.44,83.07 141.68,83.07 141.78,83.18 141.78,83.68 141.88,83.78 142.79,83.78
N18148334 on TOP (solid shape): 22.15,55.38 22.15,54.04 21.6,53.49 21.6,49.8 19.84,49.8 19.84,55.27 20.4,55.82 21.71,55.82
N179147341 on TOP (solid shape): 134.54,86.3 134.54,85.4 134.64,85.3 135.64,85.3 135.74,85.2 135.74,84.1 135.64,84 133.54,84 133.44,84.1 133.44,86.3 133.54,86.4 134.44,86.4

Small or netless copper shapes (teardrops, artwork), in the pictures only: 359 on TOP, 24 on BOTTOM

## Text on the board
Ref Des/Silkscreen Top: + | SPK | - | USB1 | 4G | DCIN_12V | USB2 | G | DP | DM | 5V | ON/OFF | USB3/USB4 | UART4 | 3.3V | GND | TX | RX | M.2 | UART3 | 3V3 | LCD-SEL | MIC | OTG | CAMERA | TF | KEY | LRADC | 485 | ETH 1000M | FEL | RST | PWR | RESET | EDP | SIM | Phone Jack | RTC | LCD | HDMI | CTP | 20260415 | HelperBoard A733 V1.8 | ________
DIMENSION: 150.0mm | 140.0mm | 105.0mm | 95.0mm
